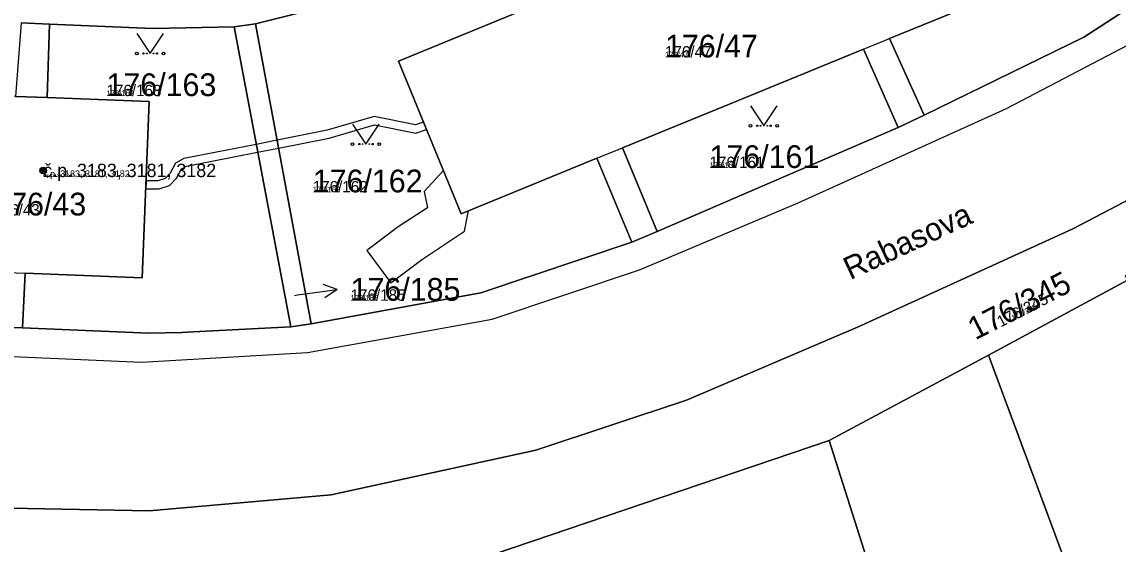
# Model space of a CAD drawing. Extents: x -759873 to -758487, y -975024 to -973516.
# Drawn here: x -759298.9 to -759216.9, y -974880.1 to -974841 of the extents above; entities that cross this region are included whole.
import ezdxf

# ---------------------------------------------------------------- set-up
doc = ezdxf.new("R2010")
doc.units = 0
for name, color, linetype in [('KAT_02_hranice parcel', 7, 'Continuous'), ('KAT_03_1000_st čísla parcelní', 7, 'Continuous'), ('KAT_03_1000_čísla parcelní', 7, 'Continuous'), ('KAT_03_1000_čísla popisná', 7, 'Continuous'), ('KAT_03_250_st čísla parcelní', 7, 'Continuous'), ('KAT_03_250_čísla parcelní', 7, 'Continuous'), ('KAT_03_250_čísla popisná', 7, 'Continuous'), ('KAT_03_500_st čísla parcelní', 7, 'Continuous'), ('KAT_03_500_čísla parcelní', 7, 'Continuous'), ('KAT_03_500_čísla popisná', 7, 'Continuous'), ('KAT_04_vnitřní kresba', 7, 'Continuous'), ('KAT_05_1000_značky kultur', 7, 'Continuous'), ('KAT_05_250_značky kultur', 7, 'Continuous'), ('KAT_05_500_značky kultur', 7, 'Continuous'), ('KAT_07_1000_značky budov', 7, 'Continuous'), ('KAT_07_250_značky budov', 7, 'Continuous'), ('KAT_07_500_značky budov', 7, 'Continuous'), ('KAT_10_věcná břemena', 7, 'Continuous'), ('KAT_12_pomocná šipka', 7, 'Continuous'), ('KAT_13_popis', 7, 'Continuous'), ('KAT_14_plocha_budovy', 7, 'Continuous'), ('KAT_14_plocha_pozemek', 7, 'Continuous')]:
    doc.layers.add(name, color=color, linetype=linetype)

msp = doc.modelspace()

# ---------------------------------------------------------------- linework, layer by layer
at = {"layer": 'KAT_02_hranice parcel'}
for p, q in [((-759296.85, -974841.17), (-759298.96, -974841.08)), ((-759283.04, -974841.37), (-759281.44, -974841.14)), ((-759278.8, -974863.8), (-759283.04, -974841.37)), ((-759281.44, -974841.14), (-759277.27, -974863.6)), ((-759233.35, -974848.89), (-759231.42, -974847.97)), ((-759251.38, -974856.67), (-759233.35, -974848.89)), ((-759253.29, -974857.47), (-759251.38, -974856.67)), ((-759216.19, -974860.33), (-759226.6, -974865.92)), ((-759300.86, -974863.82), (-759298.85, -974863.88)), ((-759278.8, -974863.8), (-759277.27, -974863.6)), ((-759226.6, -974865.92), (-759238.51, -974872.32)), ((-759217.66, -974889.98), (-759226.6, -974865.92)), ((-759238.51, -974872.32), (-759273.27, -974884.11)), ((-759230.68, -974896.92), (-759238.51, -974872.32))]:
    msp.add_line(p, q, dxfattribs=at)
for points in [[(-759231.42, -974847.97), (-759219.46, -974842.13), (-759218.62, -974841.59), (-759204.52, -974832.44), (-759196.1, -974825.59)], [(-759231.42, -974847.97), (-759234, -974842.24), (-759225.78, -974838.87), (-759230.46, -974827.44), (-759238.94, -974830.91), (-759240.73, -974826.19)], [(-759339.46, -974882.78), (-759339.8, -974881.64), (-759332.95, -974877.29), (-759323.1, -974873.6), (-759309.63, -974871.79), (-759306.19, -974871.77), (-759306.31, -974877.26), (-759289.39, -974877.59), (-759275.76, -974876.39), (-759260.46, -974873.03), (-759249.2, -974869.3), (-759236.4, -974863.83), (-759220.29, -974856.48), (-759206.61, -974849.33), (-759208.71, -974845.67), (-759199.03, -974838.5), (-759188.78, -974830.26)], [(-759281.44, -974841.14), (-759270.88, -974838.48), (-759262.91, -974835.25)], [(-759262.91, -974835.25), (-759260.76, -974839.85), (-759270.73, -974843.93), (-759266.05, -974855.36), (-759255.9, -974851.2), (-759253.29, -974857.47)], [(-759298.85, -974863.88), (-759298.66, -974859.8), (-759289.9, -974860.14), (-759289.38, -974846.96), (-759297.02, -974846.66), (-759296.85, -974841.17)], [(-759296.85, -974841.17), (-759289.12, -974841.49), (-759283.04, -974841.37)], [(-759251.38, -974856.67), (-759253.97, -974850.41), (-759245.92, -974847.12), (-759235.96, -974843.04), (-759233.35, -974848.89)], [(-759277.27, -974863.6), (-759264.57, -974861.27), (-759253.29, -974857.47)], [(-759298.85, -974863.88), (-759289.42, -974864.28), (-759286.94, -974864.24), (-759286.09, -974864.19), (-759278.8, -974863.8)]]:
    msp.add_lwpolyline(points, dxfattribs=at)
at = {"layer": 'KAT_03_1000_čísla popisná'}
msp.add_circle((-759297.31, -974852.11), 0.25, dxfattribs=at)
at = {"layer": 'KAT_03_250_čísla popisná'}
msp.add_circle((-759297.31, -974852.11), 0.0625, dxfattribs=at)
at = {"layer": 'KAT_03_500_čísla popisná'}
msp.add_circle((-759297.31, -974852.11), 0.125, dxfattribs=at)
at = {"layer": 'KAT_04_vnitřní kresba'}
for p, q in [((-759235.96, -974843.04), (-759234, -974842.24)), ((-759225.26, -974847.47), (-759214.6, -974841.89)), ((-759299.38, -974846.57), (-759297.02, -974846.66)), ((-759240.84, -974854.53), (-759225.26, -974847.47)), ((-759255.9, -974851.2), (-759253.97, -974850.41)), ((-759252.71, -974859.55), (-759240.84, -974854.53)), ((-759300.7, -974859.72), (-759298.66, -974859.8)), ((-759263.72, -974863.25), (-759252.71, -974859.55)), ((-759277.53, -974865.74), (-759263.72, -974863.25)), ((-759305.43, -974865.78), (-759289.95, -974866.45)), ((-759289.95, -974866.45), (-759277.53, -974865.74))]:
    msp.add_line(p, q, dxfattribs=at)
at = {"layer": 'KAT_05_1000_značky kultur'}
for points in [[(-759290.31, -974841.859), (-759289.31, -974843.36), (-759288.31, -974841.859)], [(-759244.4, -974847.269), (-759243.4, -974848.77), (-759242.4, -974847.269)], [(-759274.17, -974848.639), (-759273.17, -974850.14), (-759272.17, -974848.639)]]:
    msp.add_lwpolyline(points, dxfattribs=at)
for centre in [(-759290.31, -974843.359), (-759288.31, -974843.359), (-759244.4, -974848.769), (-759242.4, -974848.769), (-759274.17, -974850.139), (-759272.17, -974850.139)]:
    msp.add_circle(centre, 0.1, dxfattribs=at)
at = {"layer": 'KAT_05_250_značky kultur'}
for points in [[(-759289.56, -974842.985), (-759289.31, -974843.36), (-759289.06, -974842.985)], [(-759243.65, -974848.395), (-759243.4, -974848.77), (-759243.15, -974848.395)], [(-759273.42, -974849.765), (-759273.17, -974850.14), (-759272.92, -974849.765)]]:
    msp.add_lwpolyline(points, dxfattribs=at)
for centre in [(-759289.56, -974843.36), (-759289.06, -974843.36), (-759243.65, -974848.77), (-759243.15, -974848.77), (-759273.42, -974850.14), (-759272.92, -974850.14)]:
    msp.add_circle(centre, 0.025, dxfattribs=at)
at = {"layer": 'KAT_05_500_značky kultur'}
for points in [[(-759289.81, -974842.61), (-759289.31, -974843.36), (-759288.81, -974842.61)], [(-759243.9, -974848.02), (-759243.4, -974848.77), (-759242.9, -974848.02)], [(-759273.67, -974849.39), (-759273.17, -974850.14), (-759272.67, -974849.39)]]:
    msp.add_lwpolyline(points, dxfattribs=at)
for centre in [(-759289.81, -974843.36), (-759288.81, -974843.36), (-759243.9, -974848.77), (-759242.9, -974848.77), (-759273.67, -974850.14), (-759272.67, -974850.14)]:
    msp.add_circle(centre, 0.05, dxfattribs=at)
at = {"layer": 'KAT_07_1000_značky budov'}
msp.add_circle((-759297.317, -974852.109), 0.175, dxfattribs=at)
at = {"layer": 'KAT_07_250_značky budov'}
msp.add_circle((-759297.312, -974852.11), 0.0437, dxfattribs=at)
at = {"layer": 'KAT_07_500_značky budov'}
msp.add_circle((-759297.313, -974852.11), 0.0875, dxfattribs=at)
at = {"layer": 'KAT_10_věcná břemena'}
for points in [[(-759289.61, -974852.88), (-759289.64, -974853.48), (-759288.64, -974853.49), (-759287.86, -974853.23), (-759287.34, -974852.68), (-759286.97, -974852), (-759286.6, -974851.8), (-759281.27, -974850.75), (-759279.71, -974850.44), (-759275.92, -974849.69), (-759272.53, -974848.69), (-759269.43, -974849.32), (-759268.63, -974849.05), (-759268.86, -974848.49), (-759269.47, -974848.7), (-759272.55, -974848.07), (-759276.06, -974849.11), (-759279.82, -974849.85), (-759281.38, -974850.16), (-759286.8, -974851.22), (-759287.41, -974851.56), (-759287.82, -974852.32), (-759288.2, -974852.71), (-759288.74, -974852.89)], [(-759265.8, -974856.66), (-759265.49, -974855.13), (-759266.05, -974855.36), (-759267.38, -974852.11), (-759268.82, -974853.68), (-759268.57, -974854.9), (-759270.76, -974856.34), (-759273.11, -974858.11), (-759271.31, -974860.51), (-759269.02, -974858.8)]]:
    msp.add_lwpolyline(points, close=True, dxfattribs=at)
at = {"layer": 'KAT_12_pomocná šipka'}
for p, q in [((-759278.29, -974861.43), (-759275.318, -974861.012)), ((-759275.318, -974861.012), (-759276.38, -974860.656)), ((-759275.318, -974861.012), (-759276.24, -974861.648)), ((-759278.51, -974861.46), (-759278.29, -974861.43))]:
    msp.add_line(p, q, dxfattribs=at)
at = {"layer": 'KAT_14_plocha_budovy'}
for points in [[(-759270.73, -974843.93), (-759266.05, -974855.36), (-759255.9, -974851.2), (-759253.97, -974850.41), (-759245.92, -974847.12), (-759235.96, -974843.04), (-759234, -974842.24), (-759225.78, -974838.87), (-759230.46, -974827.44), (-759238.94, -974830.91), (-759240.8, -974831.68), (-759250.6, -974835.69), (-759258.94, -974839.1), (-759260.76, -974839.85)], [(-759304.51, -974859.57), (-759300.7, -974859.72), (-759298.66, -974859.8), (-759289.9, -974860.14), (-759289.38, -974846.96), (-759297.02, -974846.66), (-759299.38, -974846.57), (-759307.59, -974846.25), (-759311.37, -974846.1), (-759313.6, -974846.01), (-759321.97, -974845.68), (-759325.73, -974845.54), (-759327.98, -974845.45), (-759336.48, -974845.12), (-759336.99, -974858.3), (-759329.52, -974858.59), (-759327.52, -974858.67), (-759318.89, -974859.01), (-759315.08, -974859.16), (-759313, -974859.24)]]:
    msp.add_lwpolyline(points, close=True, dxfattribs=at)
at = {"layer": 'KAT_14_plocha_pozemek'}
for points in [[(-759298.96, -974841.08), (-759296.85, -974841.17), (-759289.12, -974841.49), (-759283.04, -974841.37), (-759281.44, -974841.14), (-759270.88, -974838.48), (-759262.91, -974835.25), (-759260.85, -974834.41), (-759242.72, -974826.98), (-759240.73, -974826.19), (-759235.96, -974824.17), (-759224.76, -974817.42), (-759223.9, -974816.9), (-759221.49, -974815.09), (-759213.82, -974807.81), (-759212.35, -974806.39), (-759198.31, -974792.79), (-759196.78, -974791.27), (-759191.81, -974786.42), (-759188.7, -974782.52), (-759182.55, -974773.33)], [(-759171.77, -974799.76), (-759178.71, -974808.89), (-759179.98, -974810.45), (-759194.56, -974824.34), (-759196.1, -974825.59), (-759204.52, -974832.44), (-759218.62, -974841.59), (-759219.46, -974842.13), (-759231.42, -974847.97), (-759233.35, -974848.89), (-759251.38, -974856.67), (-759253.29, -974857.47), (-759264.57, -974861.27), (-759277.27, -974863.6), (-759278.8, -974863.8), (-759286.09, -974864.19), (-759286.94, -974864.24), (-759289.42, -974864.28), (-759298.85, -974863.88), (-759300.86, -974863.82)], [(-759306.31, -974877.26), (-759289.39, -974877.59), (-759275.76, -974876.39), (-759260.46, -974873.03), (-759249.2, -974869.3), (-759236.4, -974863.83), (-759220.29, -974856.48), (-759206.61, -974849.33), (-759208.71, -974845.67), (-759199.03, -974838.5), (-759188.78, -974830.26), (-759183.17, -974825.13), (-759182.08, -974824.14), (-759181.15, -974823.29), (-759171.83, -974813.43)], [(-759309.62, -974881.37), (-759294.63, -974881.97), (-759273.68, -974881.15), (-759273.27, -974884.11), (-759238.51, -974872.32), (-759226.6, -974865.92), (-759216.19, -974860.33), (-759216.36, -974859.96), (-759214.86, -974859.41), (-759208.68, -974856.28), (-759196.21, -974843.87), (-759187.6, -974835.12), (-759186.16, -974833.19), (-759188.78, -974830.26), (-759199.03, -974838.5), (-759208.71, -974845.67), (-759206.61, -974849.33), (-759220.29, -974856.48), (-759236.4, -974863.83), (-759249.2, -974869.3), (-759260.46, -974873.03), (-759275.76, -974876.39), (-759289.39, -974877.59), (-759306.31, -974877.26)]]:
    msp.add_lwpolyline(points, dxfattribs=at)
for points in [[(-759204.52, -974832.44), (-759196.1, -974825.59), (-759201.37, -974819.92), (-759209.28, -974827.66), (-759217.93, -974818.82), (-759210.23, -974811.29), (-759213.82, -974807.81), (-759221.49, -974815.09), (-759223.9, -974816.9), (-759224.76, -974817.42), (-759235.96, -974824.17), (-759240.73, -974826.19), (-759238.94, -974830.91), (-759230.46, -974827.44), (-759225.78, -974838.87), (-759234, -974842.24), (-759231.42, -974847.97), (-759219.46, -974842.13), (-759218.62, -974841.59)], [(-759253.29, -974857.47), (-759251.38, -974856.67), (-759253.97, -974850.41), (-759245.92, -974847.12), (-759235.96, -974843.04), (-759233.35, -974848.89), (-759231.42, -974847.97), (-759234, -974842.24), (-759225.78, -974838.87), (-759230.46, -974827.44), (-759238.94, -974830.91), (-759240.73, -974826.19), (-759242.72, -974826.98), (-759240.8, -974831.68), (-759250.6, -974835.69), (-759258.94, -974839.1), (-759260.85, -974834.41), (-759262.91, -974835.25), (-759260.76, -974839.85), (-759270.73, -974843.93), (-759266.05, -974855.36), (-759255.9, -974851.2)], [(-759253.29, -974857.47), (-759255.9, -974851.2), (-759266.05, -974855.36), (-759270.73, -974843.93), (-759260.76, -974839.85), (-759262.91, -974835.25), (-759270.88, -974838.48), (-759281.44, -974841.14), (-759277.27, -974863.6), (-759264.57, -974861.27)], [(-759296.85, -974841.17), (-759298.96, -974841.08), (-759299.38, -974846.57), (-759307.59, -974846.25), (-759307.85, -974852.84), (-759304.25, -974852.98), (-759304.51, -974859.57), (-759300.7, -974859.72), (-759300.86, -974863.82), (-759298.85, -974863.88), (-759298.66, -974859.8), (-759289.9, -974860.14), (-759289.38, -974846.96), (-759297.02, -974846.66)], [(-759278.8, -974863.8), (-759283.04, -974841.37), (-759289.12, -974841.49), (-759296.85, -974841.17), (-759297.02, -974846.66), (-759289.38, -974846.96), (-759289.9, -974860.14), (-759298.66, -974859.8), (-759298.85, -974863.88), (-759289.42, -974864.28), (-759286.94, -974864.24), (-759286.09, -974864.19)], [(-759277.27, -974863.6), (-759281.44, -974841.14), (-759283.04, -974841.37), (-759278.8, -974863.8)], [(-759233.35, -974848.89), (-759235.96, -974843.04), (-759245.92, -974847.12), (-759253.97, -974850.41), (-759251.38, -974856.67)], [(-759216.19, -974860.33), (-759226.6, -974865.92), (-759217.66, -974889.98), (-759216.48, -974893.8), (-759203.97, -974928.37), (-759188.86, -974921.74), (-759189.72, -974919.43)], [(-759226.6, -974865.92), (-759238.51, -974872.32), (-759230.68, -974896.92), (-759226.86, -974908.93), (-759218.62, -974934.8), (-759203.97, -974928.37), (-759216.48, -974893.8), (-759221.42, -974895.32), (-759222.6, -974891.5), (-759217.66, -974889.98)], [(-759238.51, -974872.32), (-759273.27, -974884.11), (-759270.6, -974912.26), (-759266.42, -974952.62), (-759252.42, -974948.01), (-759242.15, -974943.89), (-759217.9, -974938.08), (-759218.62, -974934.8), (-759226.86, -974908.93), (-759242.46, -974911.45), (-759250.73, -974911.92), (-759251.15, -974904.23), (-759251.27, -974902.24), (-759251.36, -974900.54), (-759230.68, -974896.92)]]:
    msp.add_lwpolyline(points, close=True, dxfattribs=at)

# ---------------------------------------------------------------- texts
at = {"layer": 'KAT_03_1000_st čísla parcelní'}
for s, p in [('176/47', (-759250.8, -974843.66)), ('176/43', (-759301.05, -974855.48))]:
    msp.add_text(s, height=1.7, dxfattribs=at).set_placement(p)
at = {"layer": 'KAT_03_1000_čísla parcelní'}
for s, p in [('176/163', (-759292.58, -974846.549)), ('176/161', (-759247.47, -974851.929)), ('176/162', (-759277.15, -974853.75)), ('176/185', (-759274.32, -974861.86))]:
    msp.add_text(s, height=1.7, dxfattribs=at).set_placement(p)
msp.add_text('176/345', height=1.7, rotation=27, dxfattribs=at).set_placement((-759227.583, -974864.829))
at = {"layer": 'KAT_03_1000_čísla popisná'}
msp.add_text('č.p. 3183, 3181, 3182', height=1, dxfattribs=at).set_placement((-759297.31, -974852.61))
at = {"layer": 'KAT_03_250_st čísla parcelní'}
msp.add_text('176/47', height=0.425, dxfattribs=at).set_placement((-759250.8, -974843.66))
at = {"layer": 'KAT_03_250_čísla parcelní'}
for s, p in [('176/163', (-759292.58, -974846.549)), ('176/161', (-759247.47, -974851.929)), ('176/162', (-759277.15, -974853.75)), ('176/185', (-759274.32, -974861.86))]:
    msp.add_text(s, height=0.425, dxfattribs=at).set_placement(p)
msp.add_text('176/345', height=0.425, rotation=27, dxfattribs=at).set_placement((-759224.747, -974863.384))
at = {"layer": 'KAT_03_250_čísla popisná'}
msp.add_text('č.p. 3183, 3181, 3182', height=0.25, dxfattribs=at).set_placement((-759297.31, -974852.61))
at = {"layer": 'KAT_03_500_st čísla parcelní'}
for s, p in [('176/47', (-759250.8, -974843.66)), ('176/43', (-759301.05, -974855.48))]:
    msp.add_text(s, height=0.85, dxfattribs=at).set_placement(p)
at = {"layer": 'KAT_03_500_čísla parcelní'}
for s, p in [('176/163', (-759292.58, -974846.549)), ('176/161', (-759247.47, -974851.929)), ('176/162', (-759277.15, -974853.75)), ('176/185', (-759274.32, -974861.86))]:
    msp.add_text(s, height=0.85, dxfattribs=at).set_placement(p)
msp.add_text('176/345', height=0.85, rotation=27, dxfattribs=at).set_placement((-759225.692, -974863.866))
at = {"layer": 'KAT_03_500_čísla popisná'}
msp.add_text('č.p. 3183, 3181, 3182', height=0.5, dxfattribs=at).set_placement((-759297.31, -974852.61))
at = {"layer": 'KAT_13_popis'}
msp.add_text('Rabasova', height=1.7, rotation=25, dxfattribs=at).set_placement((-759236.94, -974860.33))

doc.saveas('drawing.dxf')
